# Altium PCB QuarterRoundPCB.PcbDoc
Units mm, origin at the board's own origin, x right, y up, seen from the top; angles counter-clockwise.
Board outline 60 x 60 mm, 2 copper layers (Top Layer, Bottom Layer); 38 components, 37 nets, 115 pads, 22 vias.
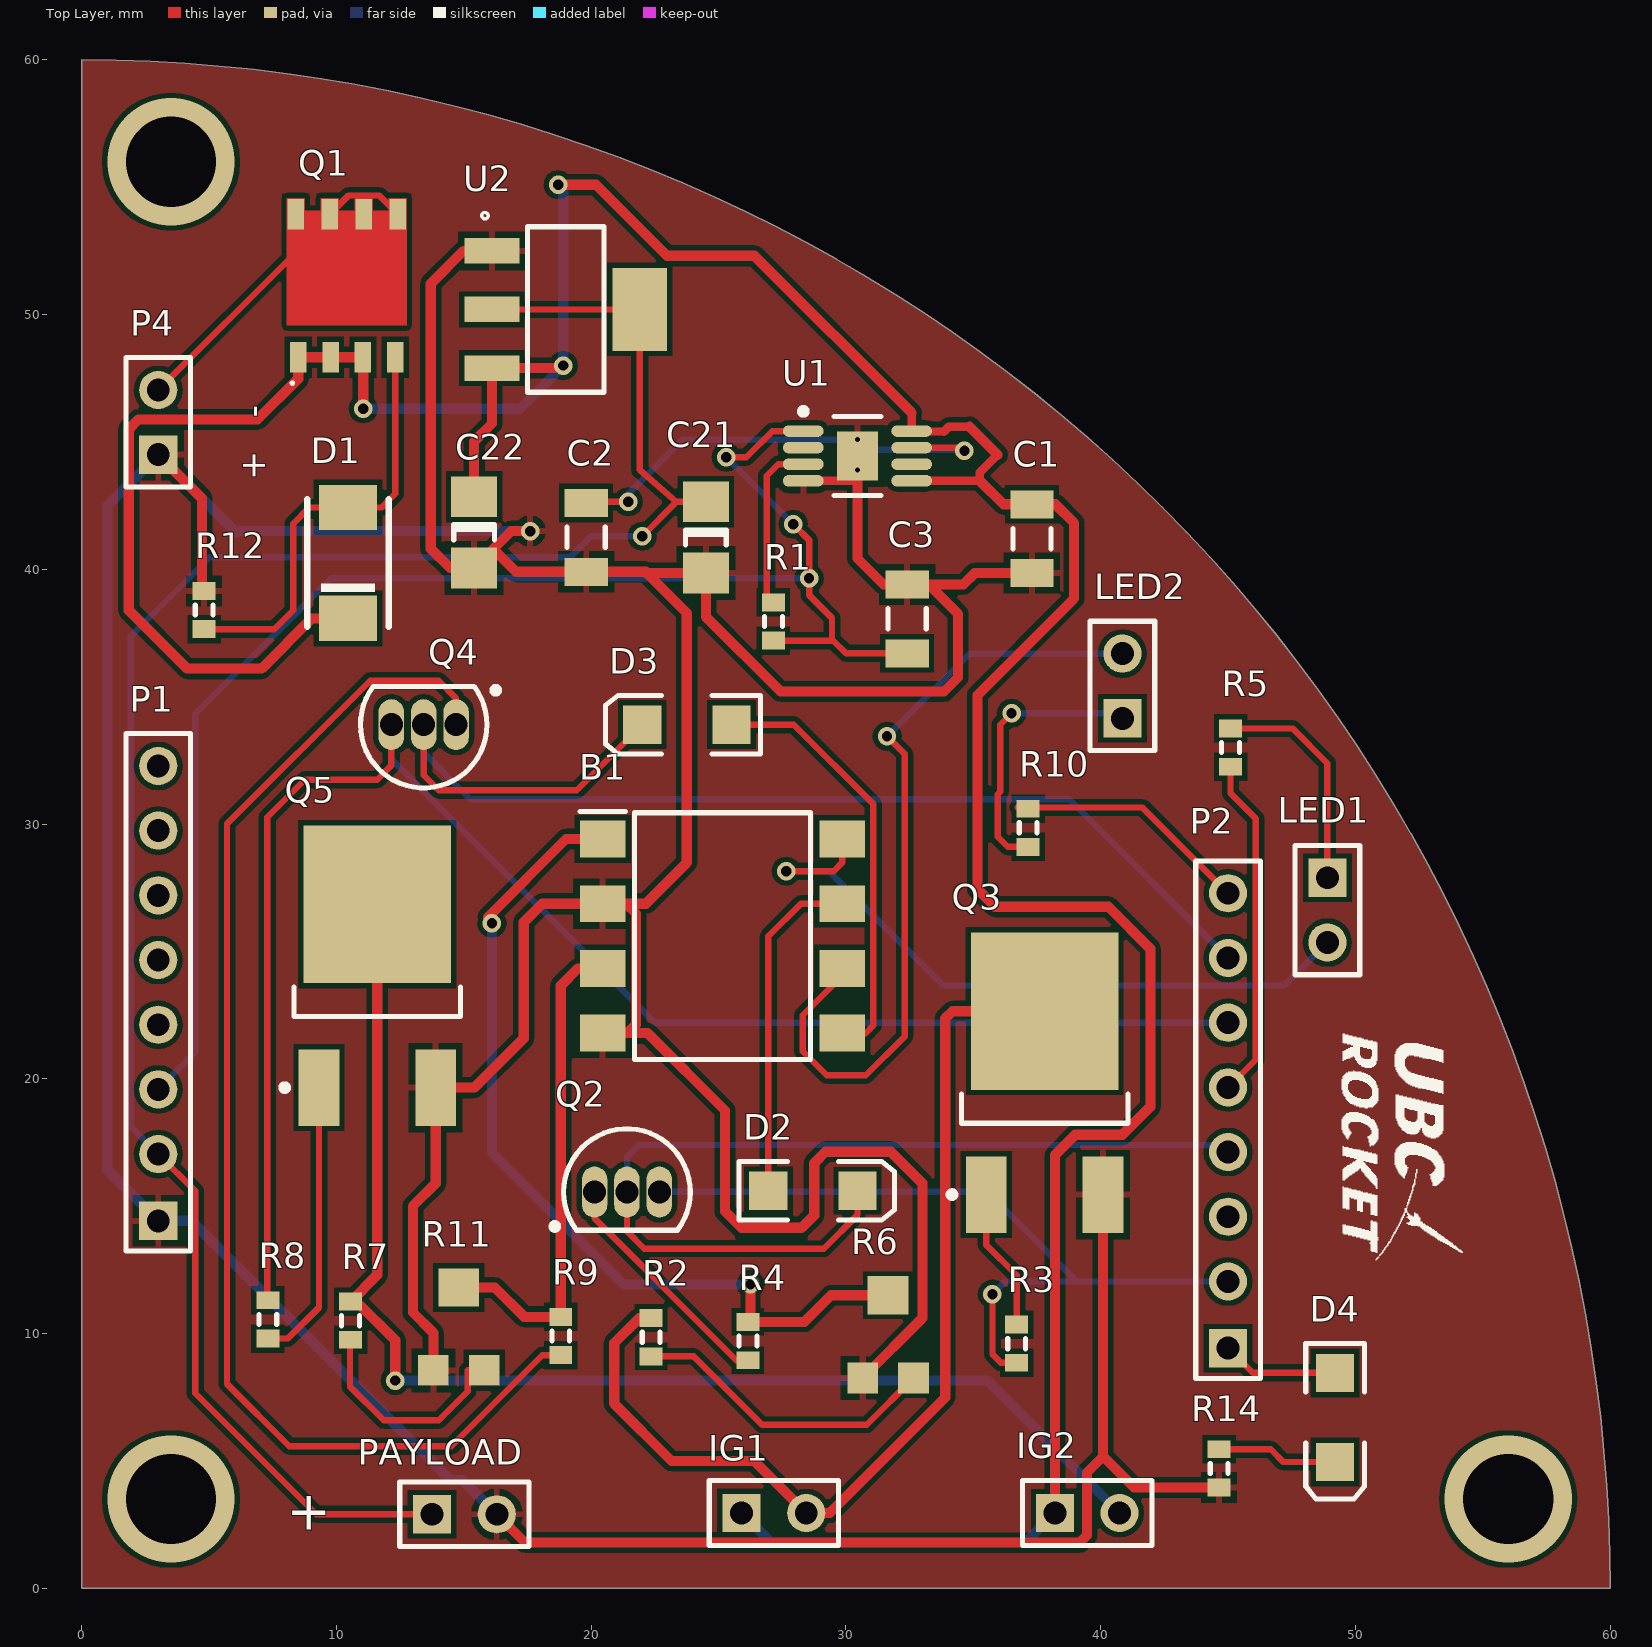
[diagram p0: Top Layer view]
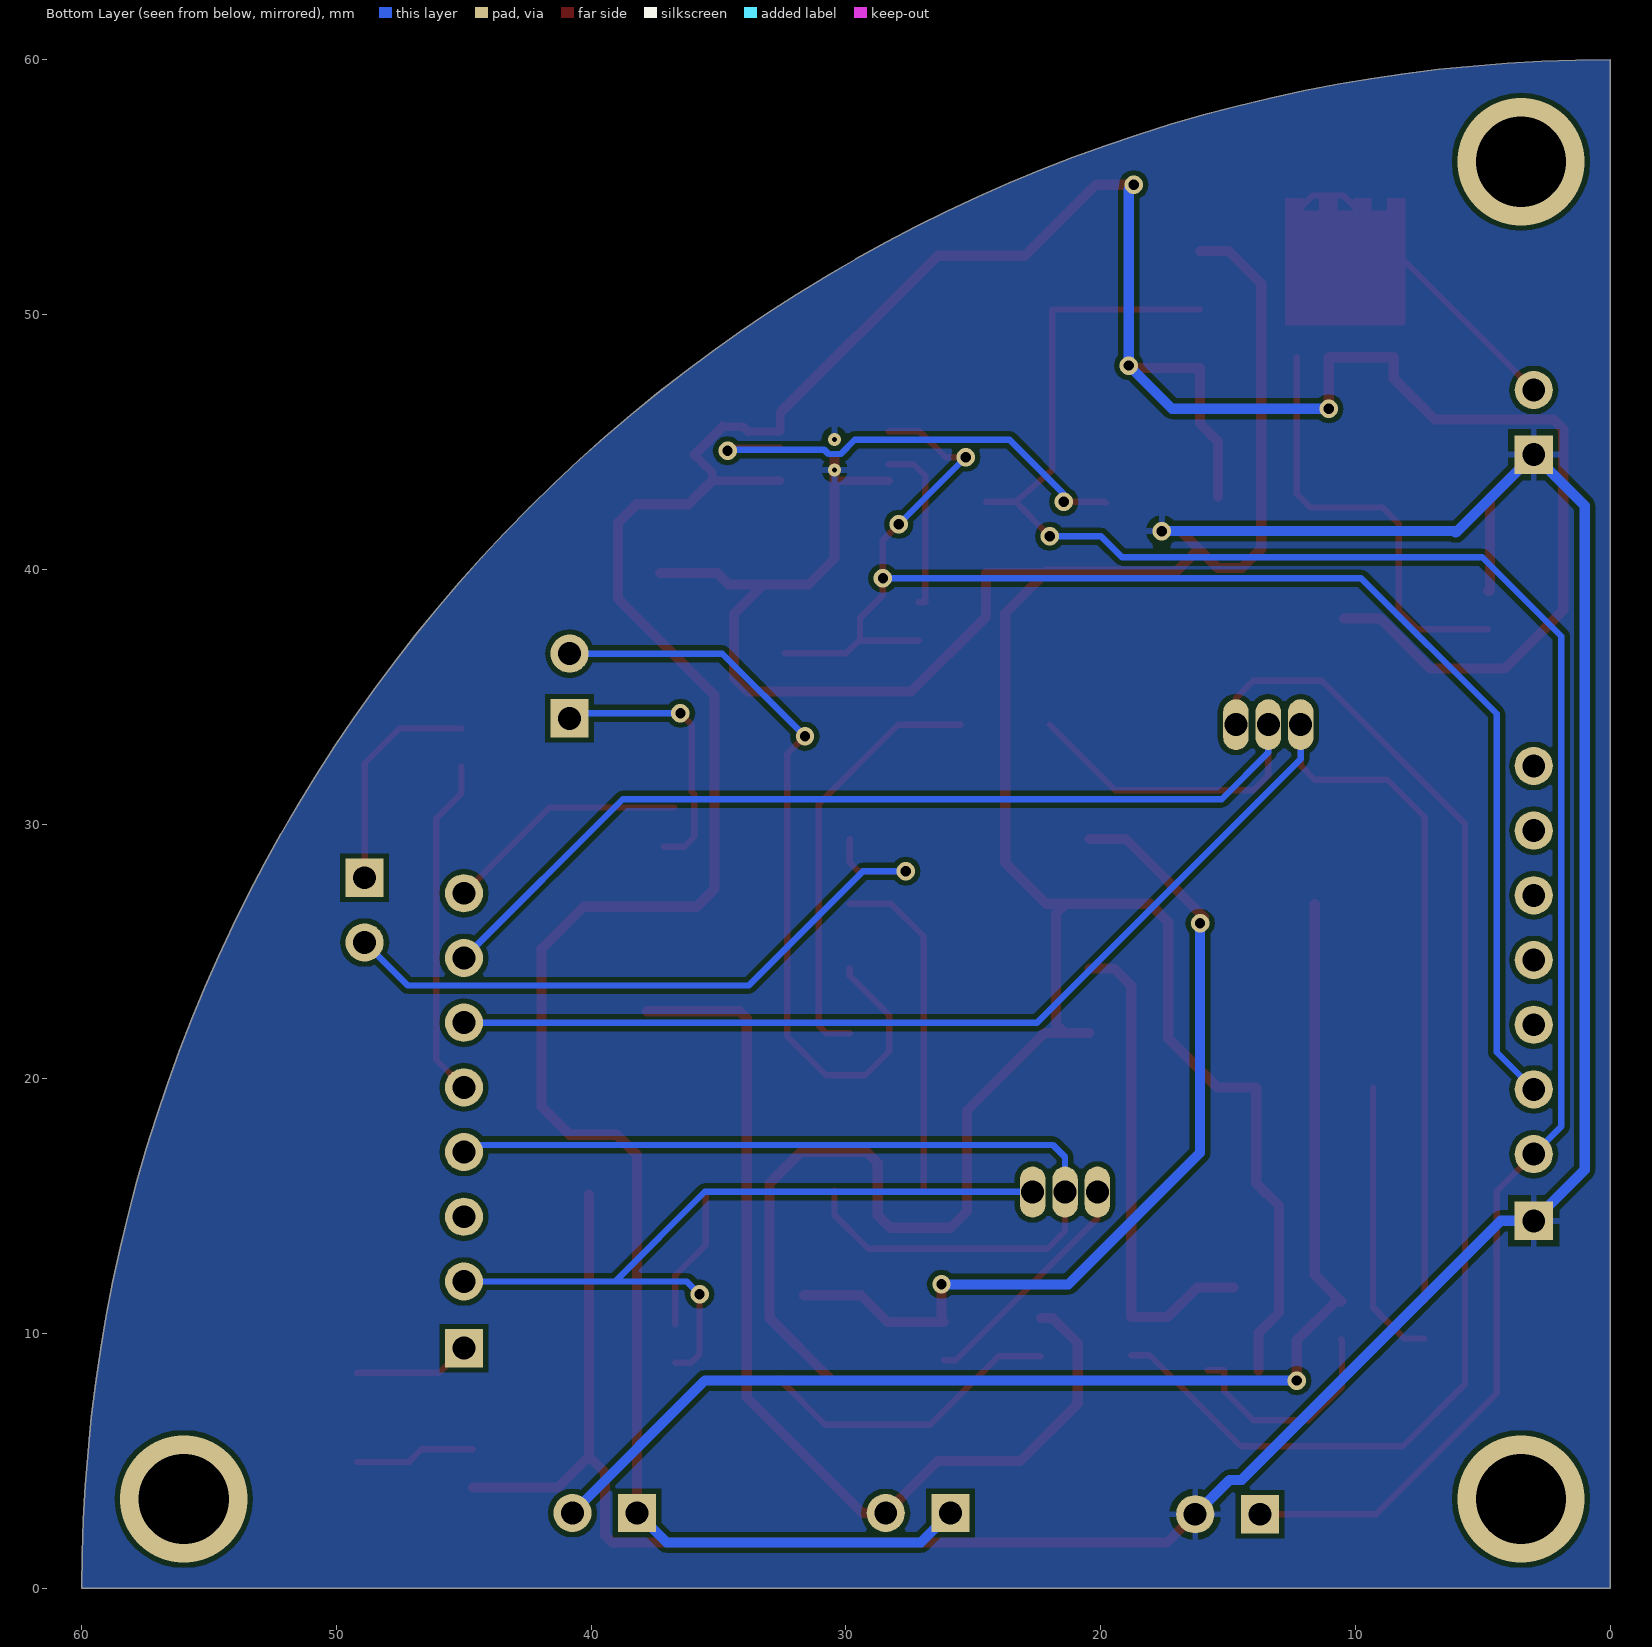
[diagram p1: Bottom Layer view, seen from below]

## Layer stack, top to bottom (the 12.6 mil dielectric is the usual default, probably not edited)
Top Solder: solder mask 0.0102, Solder Resist, Dk 3.5
Top Layer: signal copper 0.0356
Dielectric 1: dielectric 0.32, FR-4, Dk 4.8
Bottom Layer: signal copper 0.0356
Bottom Solder: solder mask 0.0102, Solder Resist, Dk 3.5

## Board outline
0,60 cw(c0,0) 60,0 0,0

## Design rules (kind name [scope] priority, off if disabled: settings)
Clearance [All] p1: gap=0.2 ignorepadtopadclearanceinfootprint=FALSE
Clearance Clearance_PWR [(InNet('BATT') OR InNet('GND'))] p2: gap=0.25 ignorepadtopadclearanceinfootprint=FALSE except(0: Arc-Hole Track-Hole SMDPad-Hole THPad-Hole Via-Hole Fill-Hole Poly-Hole Region-Hole Text-Hole)
ComponentClearance [All] p1: gap=0.25 collisioncheckmode=3 verticalgap=0.25 showdistances=FALSE
Height [All] p1: minheight=0 maxheight=30 prefheight=12.7
HoleSize HoleSize_1 [IsVia] p1: absolutevalues=TRUE maxlimit=2.54 minlimit=0.025 maxpercent=80.000 minpercent=20.000
HoleSize [All] p2: absolutevalues=TRUE maxlimit=5 minlimit=0.025 maxpercent=80.000 minpercent=20.000
PlaneClearance [All] p1: clearance=1
PlaneConnect [All] p1: planeconnectstyle=Relief reliefexpansion=0.5 reliefentries=4 reliefconductorwidth=0.25 reliefairgap=0.25
PolygonConnect [All] p1: connectstyle=Relief reliefconductorwidth=0.25 reliefentries=4 polygonreliefangle="90 Angle" airgapwidth=0.25
RoutingCorners [All] p1: cornerstyle=45-Degree minsetback=0.25 maxsetback=0.25
RoutingVias [All] p1: holewidth=0.406 width=0.725 viastyle="Through Hole" minholewidth=0.406 minwidth=0.725 maxholewidth=0.406 maxwidth=0.725
SMDNeckDown [All] p1: percent=75.000
SilkToSilkClearance [All] p1: silktosilkclearance=0
SolderMaskExpansion [All] p1: expansion=0.1
Width "Schematic Width Constraint_5" [InNet('NetIG1_2')] p1: maxlimit=0.4 minlimit=0.4 preferedwidth=0.4 minimp=50.000000 maximp=50.000000 favimp=50.000000
Width "Schematic Width Constraint_3" [InNet('AnIG1')] p2: maxlimit=0.4 minlimit=0.4 preferedwidth=0.4 minimp=50.000000 maximp=50.000000 favimp=50.000000
Width "Schematic Width Constraint_2" [InNet('AnIG2')] p3: maxlimit=0.4 minlimit=0.4 preferedwidth=0.4 minimp=50.000000 maximp=50.000000 favimp=50.000000
Width "Schematic Width Constraint_1" [InNet('NetIG2_2')] p4: maxlimit=0.4 minlimit=0.4 preferedwidth=0.4 minimp=50.000000 maximp=50.000000 favimp=50.000000
Width "Schematic Width Constraint_4" [InNet('BATT')] p5: maxlimit=0.4 minlimit=0.4 preferedwidth=0.4 minimp=50.000000 maximp=50.000000 favimp=50.000000
Width "Schematic Width Constraint" [InNet('GND')] p6: maxlimit=0.4 minlimit=0.4 preferedwidth=0.4 minimp=50.000000 maximp=50.000000 favimp=50.000000
Width Width_PWR [(InNet('BATT') OR InNet('GND'))] p7: maxlimit=0.5 minlimit=0.4 preferedwidth=0.5 minimp=50.000000 maximp=50.000000 favimp=50.000000
Width [All] p8: maxlimit=0.25 minlimit=0.25 preferedwidth=0.25
23 further rules are at their usual default settings.

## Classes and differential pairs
component class Sheet1: D4 P2 R14
component class Actuators: B1 C1 C2 C3 C21 C22 D1 D2 D3 IG1 IG2 LED1 LED2 P1 P3 P4 PAYLOAD Q1 Q2 Q3 Q4 Q5 R1 R2 R3 R4 R5 R6 R7 R8 R9 R10 R11 R12 U1 U2

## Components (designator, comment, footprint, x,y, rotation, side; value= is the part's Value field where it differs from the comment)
B1 "LTV-827S-TA1" SOP254P1016X460-8N 25.15,25.6 r0 top
C1 "Cap Semi" C1206 37.3,41.2 r90 top value=0.1uF
C2 "Cap Semi" C1206 19.8,41.25 r90 top value=0.1uF
C3 "Cap Semi" C1206 32.4,38.05 r270 top value=0.1uF
C21 "47uF 6.3V" 1206 24.5,41.25 r270 top value=100pF
C22 "47uF 6.3V" 1206 15.4,41.45 r270 top value=100pF
D1 "SMBJ16A" DO214AA_SMBJ16A(Primary) 10.45,40.25 r90 top
D2 "LED2" 3.2X1.6X1.1 28.7,15.6 r0 top
D3 "LED2" 3.2X1.6X1.1 23.75,33.9 r180 top
D4 "LED2" 3.2X1.6X1.1 49.2,6.7 r270 top
IG1 "Header 2" HDR1X2 25.9,2.95 r0 top
IG2 "Header 2" HDR1X2 38.2,2.95 r0 top
LED1 "Header 2" HDR1X2 48.9,27.89 r270 top
LED2 "Header 2" HDR1X2 40.85,34.15 r90 top
P1 "Header 8" HDR1X8 3,14.5 r90 top
P2 "Header 8" HDR1X8 45,9.5 r90 top
P4 "Header 2" HDR1X2 3,44.5 r90 top
PAYLOAD "PAYLOAD" HDR1X2 13.75,2.9 r0 top (schematic designator P3)
Q1 "BSC030P03NS3 G" INF-PG-TDSON-8-1_V 10.4,51.15 r0 top
Q2 "BC547" TO-92A 21.4,15.55 r270 top
Q3 "MJD122T4G" ONSC-DPAK-3-369C-01_V 37.8,19.85 r90 top
Q4 "BC547" TO-92A 13.42,33.9 r90 top
Q5 "MJD122T4G" ONSC-DPAK-3-369C-01_V 11.6,24.05 r90 top
R1 "Res3" J1-0603 27.15,37.95 r270 top value=1K
R2 "Res3" J1-0603 22.35,9.85 r90 top value=1K
R3 "Res3" J1-0603 36.7,9.6 r270 top value=10K
R4 "Res3" J1-0603 26.15,9.7 r270 top value=100
R5 "Res3" J1-0603 45.1,33 r270 top value=1K
R6 "TC33X-2-103E" TRIM_TC33X-2-103E 31.65,9.85 r0 top
R7 "Res3" J1-0603 10.55,10.5 r90 top value=1K
R8 "Res3" J1-0603 7.3,10.55 r90 top value=10K
R9 "Res3" J1-0603 18.8,9.9 r270 top value=100
R10 "Res3" J1-0603 37.15,29.85 r90 top value=1K
R11 "TC33X-2-103E" TRIM_TC33X-2-103E 14.8,10.15 r0 top
R12 "Res3" J1-0603 4.8,38.4 r90 top value=10K
R14 "Res3" J1-0603 44.65,4.7 r90 top value=100
U1 "TPS7A1633DGNT" TI-DGN8-1790X1470TP_N 30.45,44.45 r0 top
U2 "NCP1117ST50T3G" SOT230P700X180-4N 19,50.2 r0 top

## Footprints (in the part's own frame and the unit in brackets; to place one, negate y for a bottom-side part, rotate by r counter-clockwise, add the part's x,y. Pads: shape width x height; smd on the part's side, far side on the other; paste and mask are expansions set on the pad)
3.2X1.6X1.1 [mm] "SMT LED; 2 Flat Leads"
  rect 1.5x1.5 smd: 1(-1.75,0) 2(1.75,0)
  silkscreen extent -2.9,-1.15 3.2,1.15
1206 [mm] "Chip Capacitor; Body 3.2 x 1.6 mm (LxW typ)"
  rect 1.6x1.8 smd: 1(-1.4,0) 2(1.4,0)
  silkscreen extent -0.3,-0.8 0.3,0.8
C1206 [mm] "Chip Capacitor, Body 3.2x1.6mm, IPC High Density"
  rect 1.1x1.7 smd: 1(-1.35,0) 2(1.35,0)
  silkscreen extent -0.4,-0.75 0.4,0.75, body extent -1.7,-0.9 1.7,0.9, height 1.3
DO214AA_SMBJ16A(Primary) [mil]
  rect 70x90 smd: A(85.71,0) C(-85.71,0)
  silkscreen extent -98,-63 98,63
HDR1X2 [mm] "Connector; Header; 2 Position"
  rect 1.5x1.5 hole 0.9: 1(0,0)
  round 1.5 hole 0.9: 2(2.54,0)
  silkscreen extent -1.27,-1.27 3.81,1.27
HDR1X8 [mm] "Connector; Header; 8 Position"
  rect 1.5x1.5 hole 0.9: 1(-0.08,0)
  round 1.5 hole 0.9: 2(2.54,0) 3(5.08,0) 4(7.62,0) 5(10.16,0) 6(12.7,0) 7(15.24,0) 8(17.78,0)
  silkscreen extent -1.27,-1.27 19.05,1.27
INF-PG-TDSON-8-1_V [mm] "TDSON, 8-Leads, Body 6.15x5.15mm, Pitch 1.27mm"
  rect 0.65x1.2 smd: 1(-1.905,-2.825) 2(-0.635,-2.825) 3(0.635,-2.825) 4(1.905,-2.825) 5(2.007,2.794) 6(0.66,2.794) 7(-0.66,2.794) 8(-2.007,2.794)
  Top Layer region: 0.315,2.925 1.015,2.925 1.015,3.425 0.315,3.425
  Top Layer region: -1.015,2.925 -0.315,2.925 -0.315,3.425 -1.015,3.425
  Top Layer region: 1.65,2.925 2.35,2.925 2.35,3.425 1.65,3.425
  Top Layer region: -2.35,2.925 -1.65,2.925 -1.65,3.425 -2.35,3.425
  Top Layer region: -2.35,2.925 -2.35,-1.575 2.35,-1.575 2.35,2.925
  silkscreen extent -2.23,-3.94 -2.03,-3.74, body extent -2.58,-3.08 2.58,3.08, height 1
J1-0603 [mm] "Chip Resistor, Body 1.6x0.8mm, IPC High Density"
  rect 0.7x0.9 smd: 1(-0.75,0) 2(0.75,0)
  silkscreen extent -0.2,-0.35 0.2,0.35, body extent -0.85,-0.48 0.85,0.48, height 0.9
ONSC-DPAK-3-369C-01_V [mm] "DPAK, 3-Leads, Body 6.54x6.095mm, Pitch 2.29mm"
  rect 3x1.6 smd: 1(-4.4,2.29) 3(-4.4,-2.29)
  rect 6.2x5.8 smd: 4(2.8,0)
  silkscreen extent -4.52,-3.27 -0.45,3.76, body extent -1.6,-3.27 4.49,3.27, height 2.38
SOP254P1016X460-8N [mm]
  rect 1.79x1.45 smd: 1(-4.705,3.81) 2(-4.705,1.27) 3(-4.705,-1.27) 4(-4.705,-3.81) 5(4.705,-3.81) 6(4.705,-1.27) 7(4.705,1.27) 8(4.705,3.81)
  silkscreen extent -5.6,-4.84 3.46,4.88
SOT230P700X180-4N [mm]
  rect 2.15x1 smd: 1(-2.9,2.3) 2(-2.9,0) 3(-2.9,-2.3)
  rect 2.15x3.25 smd: 4(2.9,0)
  silkscreen extent -3.3,-3.25 1.5,3.81
TI-DGN8-1790X1470TP_N [mm] "SOIC, 8-Leads, Body 3x3mm, Pitch 0.65mm, Thermal Pad 1.79X1.47mm, IPC Medium Density"
  oval 1.6x0.45 smd: 1(-2.125,0.975) 2(-2.125,0.325) 3(-2.125,-0.325) 4(-2.125,-0.975) 5(2.125,-0.975) 6(2.125,-0.325) 7(2.125,0.325) 8(2.125,0.975)
  rect 1.6x1.92 smd: 9(0,0)
  silkscreen extent -2.25,-1.55 0.92,1.87, body extent -1.55,-1.55 1.55,1.55, height 1.1
TO-92A [mm] "TO, Flat Index; 3 In-Line, Axial Leads; Body Dia. 4.5mm; Leads 0.51 x 0.48 mm (max)"
  oval 2x1 hole 0.9: 1(0,-1.27) 2(0,0) 3(0,1.27)
  silkscreen extent -2.48,-2.95 1.5,2.48, body extent -2.48,-2.5 1.5,2.5, height 6.86
TRIM_TC33X-2-103E [mm]
  rect 1.2x1.2 smd: 1(-1,-1.6) 3(1,-1.6)
  rect 1.6x1.5 smd: 2(0,1.65)

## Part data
B1: "Lite-On LTV-827S-TA1 DC Input Transistor Output Dual Optocoupler, Surface Mount, 8-Pin PDIP", Manufacturer_Name=Lite-On, RS Part Number=6912209P
C1 C2 C3: "Capacitor (Semiconductor SIM Model)"
C21 C22: library part C1206, "Ceramic Chip Capacitor - Standard", PackageDocument=Mar-2001
D1: "Diode TVS Single Uni-Dir 16V 600W 2-Pin DO-214AA T/R", Package="DO-214AA-214 ON Semiconductor"
D2 D3 D4: "Typical RED, GREEN, YELLOW, AMBER GaAs LED"
IG1 IG2 LED1 LED2 P4: "Header, 2-Pin"
P1 P2: "Header, 8-Pin"
PAYLOAD: library part "Header 2", "Header, 2-Pin"
Q1: "P-Channel OptiMOS P3 Power-Transistor, -30 V VDS, -100 A ID, -55 to 150 degC, PG-TDSON-8-1, Reel, Green", Manufacturer=Infineon, Supplier Part Number 1=726-BSC030P03NS3G
Q2 Q4: library part 2N3904, "NPN General Purpose Amplifier"
Q3 Q5: "Complementary Darlington Power Transistor, 3-Pin DPAK, Pb-Free, Tape and Reel", Manufacturer="On Semiconductor", Supplier Part Number 1=MJD122T4GOSTR-ND
R1 R2 R3 R4 R5 R7 R8 R9 R10 R12 R14: "Resistor"
R6 R11: "Res Trimmer 10K Ohm 25% 0.1W_1/10W_ 1_Elec_/1_Mech_Turn _3 X 3.8mm_ Foot Print SMD Embossed T/R", Package="TO-221 Bourns"
U1: "Single Output LDO, 100 mA, Fixed 3.3 V Output, 3 to 60 V Input, with Enable and Power Good, 8-pin MSOP (DGN), -40 to 125 degC, Green (RoHS & no Sb/Br)", Manufacturer="Texas Instruments", Power Good=TRUE, Rating=Catalog, Supplier Part Number 1=296-30259-2-ND
U2: Package="TO-261-4 HTC Korea"

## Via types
v1: diameter 0.725, hole 0.406, Top Layer to Bottom Layer, 17 vias
v2: diameter 5, hole 3.54, Top Layer to Bottom Layer, 3 vias
v3: diameter 0.5, hole 0.2, Top Layer to Bottom Layer, 2 vias

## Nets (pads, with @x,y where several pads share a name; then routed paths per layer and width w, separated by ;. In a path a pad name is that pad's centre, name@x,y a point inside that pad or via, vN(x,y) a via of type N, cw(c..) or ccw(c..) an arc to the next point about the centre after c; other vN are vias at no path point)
3.3VRadio: P1.7
5Vradio: P1.8
ACT_24V: P1.4
AnIG1: B1.1 R4.1 R6.2 | length 34.8
  Top Layer w0.4: v1(16.1,26.1) 16.1,26.197 15.948,26.348 19.01,29.41 B1.1 ; R4.1 R4.1@26.251,10.45 ; v1(26.251,11.925) R4.1@26.251,10.45 ; R6.2 29.409,11.5 28.359,10.45 R4.1@26.251,10.45
  Bottom Layer w0.4: v1(16.1,26.1) 16.1,17.091 21.265,11.925 v1(26.251,11.925)
AnIG2: B1.3 R9.1 R11.2 | length 19.4
  Top Layer w0.4: R11.2 16.218,11.8 17.368,10.65 R9.1 18.8,23.651 19.479,24.33 B1.3
BATT: C1.2 C22.1 D1.C IG1.1 IG2.1 Q1.1 Q1.2 Q1.3 U1.5 U1.8 U2.3 | length 146.6
  Top Layer w0.337: U1.5 35.257,43.475 35.257,43.807 35.95,44.5 ; 32.575,46.139 U1.8 33.841,45.404 34.037,45.6 34.85,45.6
  Top Layer w0.4: D1.C 9.03,38.073 7.057,36.1 4.133,36.1 1.841,38.392 1.841,45.504 2.222,45.885 6.896,45.885 8.495,47.484 Q1.1 Q1.2 Q1.3 11.05,48.31 v1(11.05,46.3) ; C22.1 15.4,45.021 16.1,45.721 U2.3 18.8,47.9 v1(18.9,48) ; v1(18.7,55.1) 20.185,55.1 22.974,52.311 26.403,52.311 32.575,46.139 ; 34.85,45.6 35.95,44.5 ; 35.257,43.475 36.182,42.55 C1.2 38.222,42.55 38.95,41.822 38.95,38.85 35.166,35.066 35.166,27.445 35.861,26.75 40.306,26.75 41.95,25.106 41.95,18.9 40.85,17.8 39,17.8 38.2,17 IG2.1
  Bottom Layer w0.4: v1(11.05,46.3) 17.2,46.3 v1(18.9,48) 18.9,54.9 v1(18.7,55.1) ; IG1.1 27.059,1.791 37.041,1.791 IG2.1
BatteryStatus: P1.5
CAN_5V: C21.1 P1.2 PAYLOAD.1 U2.2 U2.4 | length 80.8
  Top Layer w0.25: P1.2 4.45,15.59 4.45,7.65 9.2,2.9 PAYLOAD.1 ; U2.2 U2.4 21.9,43.902 23.346,42.65 ; v1(22,41.3) 21.996,41.3 23.346,42.65 ; C21.1 23.346,42.65
  Bottom Layer w0.25: P1.2 1.918,18.122 1.918,37.376 5.016,40.475 19.164,40.475 19.989,41.3 v1(22,41.3)
CollIG1: B1.8 LED1.2 | length 27.1
  Top Layer w0.25: v1(27.65,28.15) 29.519,28.15 29.855,28.486 B1.8
  Bottom Layer w0.25: v1(27.65,28.15) 29.33,28.15 33.82,23.66 47.21,23.66 LED1.2
CollIG2: B1.6 LED2.2 | length 31.6
  Top Layer w0.25: B1.6 29.855,24.041 28.3,22.486 28.3,21.077 29.248,20.129 30.772,20.129 32.3,21.657 32.3,32.749 v1(31.61,33.439)
  Bottom Layer w0.25: v1(31.61,33.439) 34.861,36.69 LED2.2
EmIG1: B1.7 D2.1 | length 13.4
  Top Layer w0.25: D2.1 26.95,25.588 28.232,26.87 B1.7
EmIG2: B1.5 D3.1 | length 16.9
  Top Layer w0.25: D3.1 27.949,33.9 31.077,30.772 31.077,22.095 30.772,21.79 B1.5
GND: B1.2 B1.4 C1.1 C2.1 C3.1 C21.2 C22.2 P1.1 P4.1 PAYLOAD.2 Q3.3 Q5.3 R6.1 R11.1 R12.2 R14.1 U1.4 U1.9 U2.1 | length 247.1
  Top Layer w0.337: U1.4 30.45,43.475
  Top Layer w0.4: P4.1 4.712,42.788 4.712,39.15 R12.2 ; R11.1 13.8,10.02 13,10.82 13,15.007 13.89,15.897 Q5.3 15.408,19.65 17.35,21.592 17.35,26.148 18.072,26.87 B1.2 21.374,26.87 ; U2.1 14.984,52.5 13.7,51.216 13.7,40.808 14.458,40.05 C22.2 C22.2@16.148,40.798 ; PAYLOAD.2 17.399,1.791 39.179,1.791 39.459,2.07 39.459,4.538 40.09,5.169 40.09,5.173 ; v1(17.6,41.5) 16.85,41.5 C22.2@16.148,40.798 ; B1.4 21.409,21.79 ; C21.2 C21.2@24.498,39.85 ; U1.9 v3(30.45,43.9) 30.45,43.475 30.45,40.424 31.474,39.4 C3.1 33.25,39.4 ; R6.1 33,10.6 33,15.895 31.763,17.132 29.197,17.132 28.75,16.685 28.75,14.643 28.258,14.15 25.9,14.15 25.25,14.8 25.25,18.752 22.212,21.79 21.409,21.79 ; C1.1 35.057,39.85 34.607,39.4 33.25,39.4 ; Q3.3 40.09,5.173 ; R14.1 41.313,3.95 40.09,5.173 ; C22.2@16.148,40.798 17.047,39.9 C2.1 22.111,39.9 ; 21.374,26.87 22.136,26.87 23.75,28.484 23.75,38.286 22.186,39.85 ; 21.374,26.87 21.755,26.489 21.755,22.136 21.409,21.79 ; 22.111,39.9 22.136,39.9 22.186,39.85 ; 22.111,39.9 22.161,39.85 22.186,39.85 ; 22.186,39.85 C21.2@24.498,39.85 ; C21.2@24.498,39.85 24.498,38.138 27.436,35.2 33.85,35.2 34.4,35.75 34.4,38.25 33.25,39.4
  Bottom Layer w0.4: PAYLOAD.2 14.94,4.25 14.466,4.25 4.296,14.42 P1.1 1,16.42 1,42.5 P4.1 6.06,41.44 6.12,41.5 v1(17.6,41.5)
  other v3: 30.45,45.1
NetC2_2: C2.2 U1.7 | length 18.5
  Top Layer w0.25: C2.2 19.85,42.65 v1(21.45,42.65) ; U1.7 34.525,44.775 v1(34.65,44.65)
  Bottom Layer w0.25: v1(21.45,42.65) 21.45,42.955 23.579,45.085 29.652,45.085 30.212,44.525 30.688,44.525 30.863,44.7 34.6,44.7 v1(34.65,44.65)
NetD1_A: D1.A Q1.4 R12.1 | length 17.1
  Top Layer w0.25: R12.1 7.556,37.65 8.293,38.387 8.293,41.792 8.928,42.427 D1.A 11.768,42.427 12.305,42.964 Q1.4
NetD2_2: D2.2 P2.4 Q2.2 | length 37.7
  Top Layer w0.25: Q2.2 21.4,14.008 22.086,13.322 29.122,13.322 30.45,14.65 D2.2
  Bottom Layer w0.25: Q2.2 21.4,16.929 21.871,17.4 44.72,17.4 P2.4
NetD3_2: D3.2 P2.7 Q4.2 | length 47.9
  Top Layer w0.25: Q4.2 13.42,31.919 14.008,31.331 19.431,31.331 D3.2
  Bottom Layer w0.25: Q4.2 13.42,32.808 15.253,30.975 38.765,30.975 P2.7
NetD4_1: D4.1 P2.1 | length 4.6
  Top Layer w0.25: P2.1 45.97,8.45 D4.1
NetD4_2: D4.2 R14.2 | length 4.8
  Top Layer w0.25: R14.2 46.672,5.45 47.172,4.95 D4.2
NetIG1_2: IG1.2 Q3.4 R2.2 | length 39.8
  Top Layer w0.4: R2.2 21.878,10.6 20.9,9.622 20.9,7.243 23.152,4.991 26.399,4.991 IG1.2 29.366,2.95 33.9,7.484 33.9,22.368 34.182,22.65 Q3.4
NetIG2_2: IG2.2 Q5.4 R7.2 | length 50.6
  Top Layer w0.4: Q5.4 11.6,12.3 R7.2 10.785,11.25 12.3,9.735 v1(12.3,8.15)
  Bottom Layer w0.4: v1(12.3,8.15) 35.54,8.15 IG2.2
NetLED1_1: LED1.1 R5.1 | length 8.9
  Top Layer w0.25: R5.1 47.536,33.75 48.9,32.386 LED1.1
NetLED2_1: LED2.1 R10.1 | length 10.9
  Top Layer w0.25: v1(36.5,34.35) 36.05,33.9 36.05,31.26 35.954,31.163 35.954,29.496 36.35,29.1 R10.1
  Bottom Layer w0.25: v1(36.5,34.35) 40.65,34.35 LED2.1
NetP2_2: P2.2 Q2.3 R3.2 | length 30.8
  Top Layer w0.25: v1(35.75,11.544) 35.75,9.182 36.082,8.85 R3.2
  Bottom Layer w0.25: Q2.3 22.67,15.557 35.547,15.557 39.065,12.04 ; v1(35.75,11.544) 36.246,12.04 39.065,12.04 ; P2.2 39.065,12.04
NetP2_5: P2.5 R5.2 | length 13.5
  Top Layer w0.25: P2.5 46.088,20.748 46.088,30.213 45.098,31.204 45.098,32.25 R5.2
NetP2_6: P2.6 Q4.3 R8.2 | length 64.8
  Top Layer w0.25: R8.2 7.277,11.3 7.277,30.264 8.75,31.737 11.591,31.737 12.15,32.296 Q4.3
  Bottom Layer w0.25: Q4.3 12.15,32.55 22.5,22.2 P2.6
NetP2_8: P2.8 R10.2 | length 9.6
  Top Layer w0.25: R10.2@36.75,30.65 41.63,30.65 P2.8
NetP4_2: P4.2 Q1.5 Q1.6 Q1.7 Q1.8 | length 18.6
  Top Layer w0.25: P4.2 8.393,52.433 8.393,53.124 ; Q1.8 8.393,53.124 ; Q1.7 10.469,54.673 11.677,54.673 Q1.5 ; Q1.6 Q1.5 ; 8.393,53.124 12.407,53.124 Q1.5
NetQ2_1: Q2.1 R4.2 | length 9.4
  Top Layer w0.25: Q2.1 20.13,14.512 25.692,8.95 R4.2
NetQ3_1: Q3.1 R3.1 | length 5.6
  Top Layer w0.25: Q3.1 35.51,13.471 36.7,12.281 R3.1
NetQ4_1: Q4.1 R9.2 | length 50.2
  Top Layer w0.25: Q4.1 14.69,34.941 14.008,35.623 11.316,35.623 5.7,30.008 5.7,8.016 8.141,5.575 14.497,5.575 18.072,9.15 R9.2
NetQ5_1: Q5.1 R8.1 | length 11.1
  Top Layer w0.25: R8.1 8.09,9.8 9.31,11.02 Q5.1
NetR1_1: R1.1 U1.3 | length 6.9
  Top Layer w0.25: R1.1 26.886,38.7 26.886,43.675 27.336,44.125 U1.3
NetR2_1: R2.1 R6.3 | length 12.2
  Top Layer w0.25: R2.1 24.016,9.1 26.702,6.413 30.813,6.413 R6.3
NetR7_1: R7.1 R11.3 | length 9
  Top Layer w0.25: R7.1 10.528,9.75 10.528,7.912 11.849,6.591 14.008,6.591 15.151,7.734 15.151,8.55 R11.3
RadioBatteryStatus: P1.6
VCC: C3.2 P1.3 R1.2 U1.1 | length 59.5
  Top Layer w0.25: v1(25.3,44.397) 26.084,44.397 27.112,45.425 U1.1 ; R1.2 29.45,37.2 ; v1(27.927,41.77) 28.55,41.147 v1(28.55,39.65) 28.55,38.988 29.45,38.088 29.45,37.2 ; C3.2 30.002,36.7 29.502,37.2 29.45,37.2
  Bottom Layer w0.25: P1.3 4.458,21.038 4.458,34.328 9.78,39.65 v1(28.55,39.65) ; v1(25.3,44.397) v1(27.927,41.77)
pads on no net: P2.3 U1.2 U1.6
copper on no net:
  other v2: 3.5,3.5 56,3.5 3.5,56

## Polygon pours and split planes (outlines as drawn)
GND on Bottom Layer "bottom" (solid, pour order 12): 0,60 cw(c0,0) 60,0 0,0
GND on Top Layer "Top Layer-No Net" (solid, pour order 13): 0,60 cw(c0,0) 60,0 0,0

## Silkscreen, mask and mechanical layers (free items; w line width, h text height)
Top Overlay:
  drawing of 13 lines, arcs and shapes, not listed
  text "+   -" at 7.2,43.5 h1 r90
  text "+" at 8.05,2.3 h1.52
Mechanical 1:
  lines w0.254: 0,60 0,0 60,0 ; 0,60.185 cw(c0,0) 60.185,0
